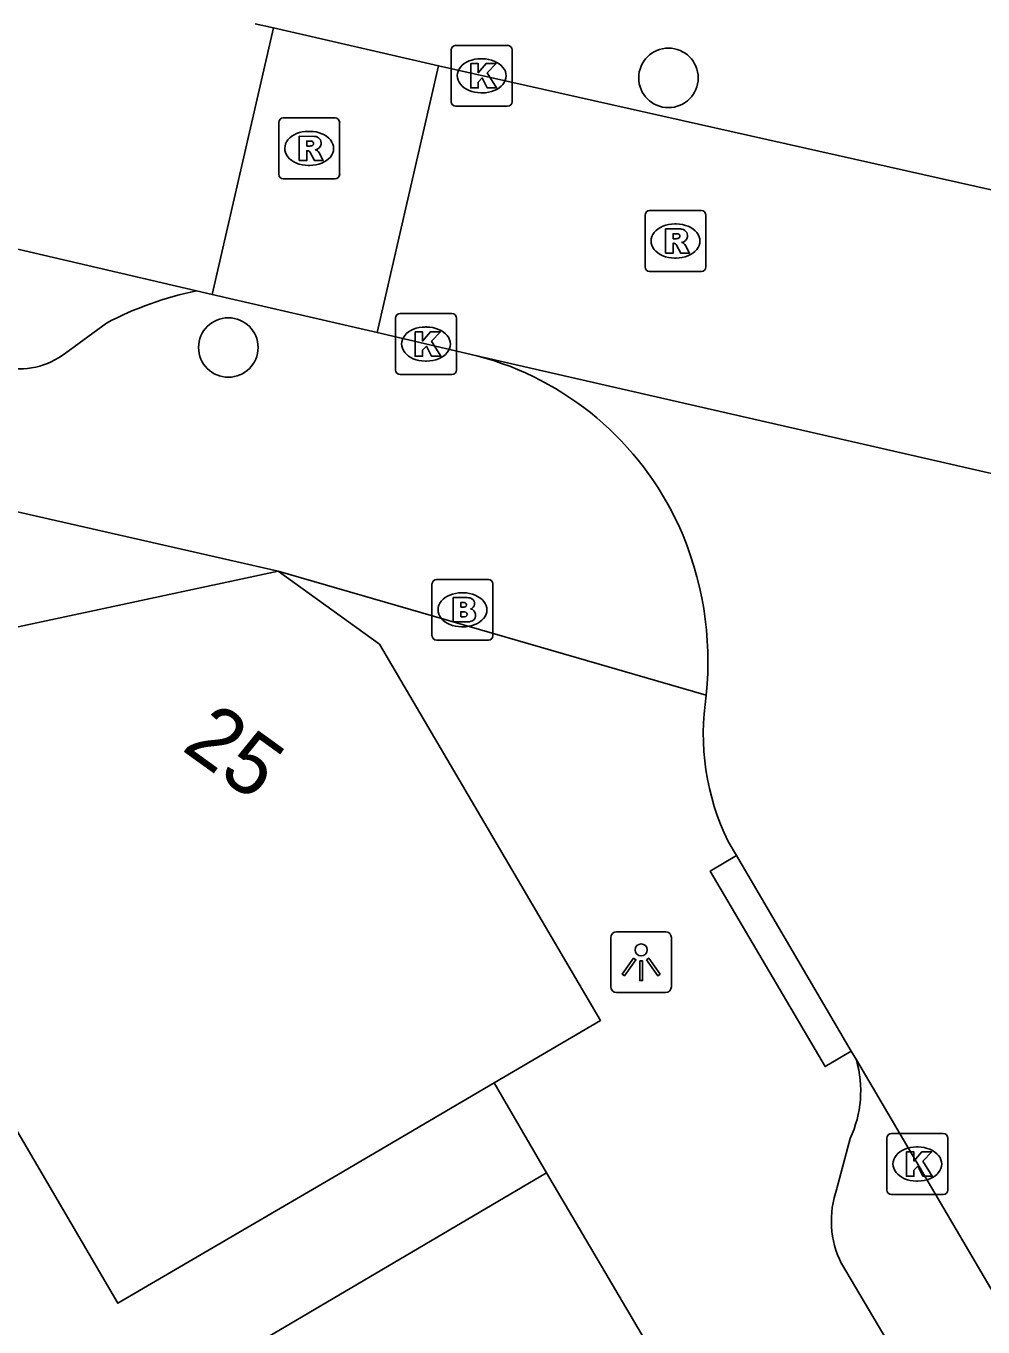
# Model space of a CAD drawing. Extents: x 159718 to 160783, y 383290 to 384030.
# Drawn here: x 160111.85 to 160127.57, y 383460.37 to 383481.74 of the extents above; entities that cross this region are included whole.
import ezdxf

# ---------------------------------------------------------------- set-up
doc = ezdxf.new("R2010")
doc.units = 0
for name, color, linetype in [('IMGEO_Boom', 7, 'Continuous'), ('IMGEO_Brandkraan', 7, 'Continuous'), ('IMGEO_Kolk', 7, 'Continuous'), ('IMGEO_Lichtpunt', 7, 'Continuous'), ('IMGEO_Pand', 7, 'Continuous'), ('IMGEO_Pand_nummerreeks', 7, 'Continuous'), ('IMGEO_Rijbaan_lokaal_open', 7, 'Continuous'), ('IMGEO_Rioolput', 7, 'Continuous'), ('IMGEO_Voetpad_open', 7, 'Continuous')]:
    doc.layers.add(name, color=color, linetype=linetype)

msp = doc.modelspace()

# ---------------------------------------------------------------- linework, layer by layer
at = {"layer": 'IMGEO_Boom'}
for centre in [(160122.406, 383480.893), (160115.175, 383476.462)]:
    msp.add_circle(centre, 0.489, dxfattribs=at)
at = {"layer": 'IMGEO_Brandkraan'}
for p, q in [((160118.521, 383471.726), (160118.521, 383472.578)), ((160118.596, 383472.652), (160119.448, 383472.652)), ((160119.522, 383472.578), (160119.522, 383471.726)), ((160119.009, 383472.432), (160119.034, 383472.432)), ((160119.032, 383471.872), (160119.007, 383471.872)), ((160119.448, 383471.652), (160118.596, 383471.652))]:
    msp.add_line(p, q, dxfattribs=at)
for points in [[(160118.521, 383471.726), (160118.521, 383472.578)], [(160118.596, 383472.652), (160119.448, 383472.652)], [(160119.522, 383472.578), (160119.522, 383471.726)], [(160118.869, 383472.352), (160118.869, 383471.952), (160119.082, 383471.952)], [(160119.1, 383472.352), (160118.869, 383472.352)], [(160119.048, 383472.271), (160118.994, 383472.271), (160118.994, 383472.195)], [(160118.994, 383472.195), (160119.047, 383472.195)], [(160119.056, 383472.119), (160118.994, 383472.119), (160118.994, 383472.038)], [(160118.994, 383472.038), (160119.056, 383472.038)], [(160119.448, 383471.652), (160118.596, 383471.652)]]:
    msp.add_lwpolyline(points, dxfattribs=at)
for centre, radius, start, end in [((160118.598, 383472.576), 0.0765, 91.552, 178.448), ((160118.598, 383472.576), 0.0765, 91.552, 178.448), ((160119.446, 383472.576), 0.0765, 1.552, 88.448), ((160119.446, 383472.576), 0.0765, 1.552, 88.448), ((160119.049, 383472.233), 0.0379, 267.8285, 90.9355), ((160119.104, 383472.207), 0.145, 59.4692, 91.5367), ((160119.129, 383472.254), 0.0922, 285.5137, 58.1501), ((160119.134, 383472.062), 0.105, 301.3115, 78.989), ((160119.057, 383472.078), 0.0404, 269.8759, 90.5077), ((160119.088, 383472.203), 0.251, 268.6676, 293.5347), ((160118.598, 383471.728), 0.0765, 181.552, 268.448), ((160118.598, 383471.728), 0.0765, 181.552, 268.448), ((160119.446, 383471.728), 0.0765, 271.552, 358.448), ((160119.446, 383471.728), 0.0765, 271.552, 358.448)]:
    msp.add_arc(centre, radius, start, end, dxfattribs=at)
for centre, major_axis, ratio, start_param, end_param in [((160119.008, 383472.152), (-0.387, 0.002), 0.722429, 4.712389, 7.853982), ((160119.033, 383472.152), (-0.39, 0.002), 0.717154, 1.570796, 4.712389)]:
    msp.add_ellipse(centre, major_axis=major_axis, ratio=ratio, start_param=start_param, end_param=end_param, dxfattribs=at)
at = {"layer": 'IMGEO_Kolk'}
for p, q in [((160118.837, 383480.501), (160118.837, 383481.353)), ((160118.912, 383481.427), (160119.764, 383481.427)), ((160119.838, 383481.353), (160119.838, 383480.501)), ((160119.325, 383481.207), (160119.35, 383481.207)), ((160119.348, 383480.647), (160119.323, 383480.647)), ((160119.764, 383480.427), (160118.912, 383480.427)), ((160117.922, 383476.093), (160117.922, 383476.945)), ((160117.997, 383477.019), (160118.849, 383477.019)), ((160118.923, 383476.945), (160118.923, 383476.093)), ((160118.41, 383476.799), (160118.435, 383476.799)), ((160118.433, 383476.239), (160118.408, 383476.239)), ((160118.849, 383476.019), (160117.997, 383476.019)), ((160125.994, 383462.619), (160125.994, 383463.471)), ((160126.069, 383463.545), (160126.921, 383463.545)), ((160126.995, 383463.471), (160126.995, 383462.619)), ((160126.482, 383463.325), (160126.507, 383463.325)), ((160126.505, 383462.765), (160126.48, 383462.765)), ((160126.921, 383462.545), (160126.069, 383462.545))]:
    msp.add_line(p, q, dxfattribs=at)
for points in [[(160118.837, 383480.501), (160118.837, 383481.353)], [(160118.912, 383481.427), (160119.764, 383481.427)], [(160119.838, 383481.353), (160119.838, 383480.501)], [(160119.158, 383481.127), (160119.281, 383481.127), (160119.281, 383480.976), (160119.411, 383481.127), (160119.575, 383481.127), (160119.429, 383480.976), (160119.582, 383480.727), (160119.43, 383480.727), (160119.345, 383480.891), (160119.281, 383480.824), (160119.281, 383480.727), (160119.158, 383480.727), (160119.158, 383481.127)], [(160119.764, 383480.427), (160118.912, 383480.427)], [(160117.922, 383476.093), (160117.922, 383476.945)], [(160117.997, 383477.019), (160118.849, 383477.019)], [(160118.923, 383476.945), (160118.923, 383476.093)], [(160118.243, 383476.719), (160118.366, 383476.719), (160118.366, 383476.568), (160118.496, 383476.719), (160118.66, 383476.719), (160118.514, 383476.568), (160118.667, 383476.319), (160118.515, 383476.319), (160118.43, 383476.483), (160118.366, 383476.416), (160118.366, 383476.319), (160118.243, 383476.319), (160118.243, 383476.719)], [(160118.849, 383476.019), (160117.997, 383476.019)], [(160125.994, 383462.619), (160125.994, 383463.471)], [(160126.069, 383463.545), (160126.921, 383463.545)], [(160126.995, 383463.471), (160126.995, 383462.619)], [(160126.315, 383463.245), (160126.438, 383463.245), (160126.438, 383463.094), (160126.568, 383463.245), (160126.732, 383463.245), (160126.586, 383463.094), (160126.739, 383462.845), (160126.587, 383462.845), (160126.502, 383463.009), (160126.438, 383462.942), (160126.438, 383462.845), (160126.315, 383462.845), (160126.315, 383463.245)], [(160126.921, 383462.545), (160126.069, 383462.545)]]:
    msp.add_lwpolyline(points, dxfattribs=at)
for centre, start, end in [((160118.914, 383481.351), 91.552, 178.448), ((160118.914, 383481.351), 91.552, 178.448), ((160119.762, 383481.351), 1.552, 88.448), ((160119.762, 383481.351), 1.552, 88.448), ((160118.914, 383480.503), 181.552, 268.448), ((160118.914, 383480.503), 181.552, 268.448), ((160119.762, 383480.503), 271.552, 358.448), ((160119.762, 383480.503), 271.552, 358.448), ((160117.999, 383476.943), 91.552, 178.448), ((160117.999, 383476.943), 91.552, 178.448), ((160118.847, 383476.943), 1.552, 88.448), ((160118.847, 383476.943), 1.552, 88.448), ((160117.999, 383476.095), 181.552, 268.448), ((160117.999, 383476.095), 181.552, 268.448), ((160118.847, 383476.095), 271.552, 358.448), ((160118.847, 383476.095), 271.552, 358.448), ((160126.071, 383463.469), 91.552, 178.448), ((160126.071, 383463.469), 91.552, 178.448), ((160126.919, 383463.469), 1.552, 88.448), ((160126.919, 383463.469), 1.552, 88.448), ((160126.071, 383462.621), 181.552, 268.448), ((160126.071, 383462.621), 181.552, 268.448), ((160126.919, 383462.621), 271.552, 358.448), ((160126.919, 383462.621), 271.552, 358.448)]:
    msp.add_arc(centre, 0.0765, start, end, dxfattribs=at)
for centre, major_axis, ratio, start_param, end_param in [((160119.324, 383480.927), (-0.387, 0.002), 0.722429, 4.712389, 7.853982), ((160119.349, 383480.927), (-0.39, 0.002), 0.717154, 1.570796, 4.712389), ((160118.409, 383476.519), (-0.387, 0.002), 0.722429, 4.712389, 7.853982), ((160118.434, 383476.519), (-0.39, 0.002), 0.717154, 1.570796, 4.712389), ((160126.481, 383463.045), (-0.387, 0.002), 0.722429, 4.712389, 7.853982), ((160126.506, 383463.045), (-0.39, 0.002), 0.717154, 1.570796, 4.712389)]:
    msp.add_ellipse(centre, major_axis=major_axis, ratio=ratio, start_param=start_param, end_param=end_param, dxfattribs=at)
at = {"layer": 'IMGEO_Lichtpunt'}
for p, q in [((160122.36, 383466.86), (160121.552, 383466.86)), ((160122.36, 383466.86), (160121.552, 383466.86)), ((160121.458, 383466.765), (160121.458, 383465.958)), ((160121.458, 383466.765), (160121.458, 383465.958)), ((160122.454, 383465.958), (160122.454, 383466.765)), ((160122.454, 383465.958), (160122.454, 383466.765)), ((160121.552, 383465.864), (160122.36, 383465.864)), ((160121.552, 383465.864), (160122.36, 383465.864))]:
    msp.add_line(p, q, dxfattribs=at)
for points in [[(160121.832, 383466.429), (160121.871, 383466.401), (160121.683, 383466.139), (160121.645, 383466.166), (160121.832, 383466.429)], [(160121.934, 383466.381), (160121.981, 383466.381), (160121.981, 383466.059), (160121.934, 383466.059), (160121.934, 383466.381)], [(160122.044, 383466.401), (160122.082, 383466.428), (160122.269, 383466.166), (160122.23, 383466.138), (160122.044, 383466.401)]]:
    msp.add_lwpolyline(points, dxfattribs=at)
msp.add_circle((160121.957, 383466.563), 0.0994, dxfattribs=at)
for centre, start, end in [((160121.552, 383466.765), 90, 180), ((160121.552, 383466.765), 90, 180), ((160122.36, 383466.765), 0, 90), ((160122.36, 383466.765), 0, 90), ((160121.552, 383465.958), 180, 270), ((160121.552, 383465.958), 180, 270), ((160122.36, 383465.958), 270, 0), ((160122.36, 383465.958), 270, 360)]:
    msp.add_arc(centre, 0.0946, start, end, dxfattribs=at)
at = {"layer": 'IMGEO_Pand'}
for points in [[(160115.993, 383472.788), (160107.52, 383470.974), (160108.363, 383474.524)], [(160115.993, 383472.788), (160117.657, 383471.587), (160121.29, 383465.405), (160119.544, 383464.378)], [(160119.544, 383464.378), (160116.981, 383462.87), (160113.362, 383460.758), (160111.515, 383463.912), (160107.52, 383461.562), (160106.899, 383462.618), (160104.842, 383466.115), (160102.458, 383466.683), (160102.051, 383466.78)], [(160123.801, 383457.127), (160119.492, 383454.592), (160116.953, 383453.098), (160115.556, 383455.612), (160113.326, 383454.3), (160110.771, 383452.796), (160109.958, 383454.177), (160108.721, 383456.279), (160113.525, 383459.105), (160113.635, 383458.918), (160116.096, 383460.366), (160120.405, 383462.901)], [(160123.801, 383457.127), (160120.405, 383462.901)]]:
    msp.add_lwpolyline(points, dxfattribs=at)
at = {"layer": 'IMGEO_Rijbaan_lokaal_open'}
for points in [[(160076.614, 383486.267), (160114.655, 383477.395)], [(160115.615, 383481.783), (160115.92, 383481.713)], [(160114.912, 383477.335), (160115.92, 383481.713)], [(160115.92, 383481.713), (160118.629, 383481.089)], [(160118.629, 383481.089), (160117.62, 383476.707)], [(160118.629, 383481.089), (160134.274, 383477.578)], [(160114.912, 383477.335), (160114.655, 383477.395)], [(160117.62, 383476.707), (160114.912, 383477.335)], [(160119.26, 383476.327), (160117.62, 383476.707)], [(160132.838, 383473.219), (160119.26, 383476.327)], [(160123.386, 383468.345), (160123.523, 383468.112)], [(160123.523, 383468.112), (160125.409, 383464.899)], [(160125.409, 383464.899), (160125.493, 383464.755)], [(160125.493, 383464.755), (160139.179, 383441.454)]]:
    msp.add_lwpolyline(points, dxfattribs=at)
for centre, radius, start, end in [((160117.967, 383471.429), 5.066, 24.5802, 75.2127), ((160117.607, 383471.299), 5.448, 354.229, 24.2483), ((160127.035, 383470.119), 4.057, 171.0415, 205.9315)]:
    msp.add_arc(centre, radius, start, end, dxfattribs=at)
at = {"layer": 'IMGEO_Rioolput'}
for p, q in [((160116.003, 383479.308), (160116.003, 383480.16)), ((160116.078, 383480.234), (160116.93, 383480.234)), ((160117.004, 383480.16), (160117.004, 383479.308)), ((160116.491, 383480.014), (160116.516, 383480.014)), ((160116.514, 383479.454), (160116.489, 383479.454)), ((160116.93, 383479.234), (160116.078, 383479.234)), ((160122.021, 383477.786), (160122.021, 383478.638)), ((160122.096, 383478.712), (160122.948, 383478.712)), ((160123.022, 383478.638), (160123.022, 383477.786)), ((160122.509, 383478.492), (160122.534, 383478.492)), ((160122.532, 383477.932), (160122.507, 383477.932)), ((160122.948, 383477.712), (160122.096, 383477.712))]:
    msp.add_line(p, q, dxfattribs=at)
for points in [[(160116.003, 383479.308), (160116.003, 383480.16)], [(160116.078, 383480.234), (160116.93, 383480.234)], [(160117.004, 383480.16), (160117.004, 383479.308)], [(160116.592, 383479.932), (160116.34, 383479.934), (160116.34, 383479.534)], [(160116.518, 383479.853), (160116.464, 383479.853), (160116.464, 383479.772)], [(160116.34, 383479.534), (160116.464, 383479.534), (160116.464, 383479.696), (160116.475, 383479.696)], [(160116.464, 383479.772), (160116.516, 383479.772)], [(160116.522, 383479.667), (160116.593, 383479.534), (160116.733, 383479.534), (160116.668, 383479.66)], [(160116.93, 383479.234), (160116.078, 383479.234)], [(160122.021, 383477.786), (160122.021, 383478.638)], [(160122.096, 383478.712), (160122.948, 383478.712)], [(160123.022, 383478.638), (160123.022, 383477.786)], [(160122.61, 383478.41), (160122.358, 383478.412), (160122.358, 383478.012)], [(160122.358, 383478.012), (160122.482, 383478.012), (160122.482, 383478.174), (160122.493, 383478.174)], [(160122.536, 383478.331), (160122.482, 383478.331), (160122.482, 383478.25)], [(160122.482, 383478.25), (160122.534, 383478.25)], [(160122.54, 383478.145), (160122.611, 383478.012), (160122.751, 383478.012), (160122.686, 383478.138)], [(160122.948, 383477.712), (160122.096, 383477.712)]]:
    msp.add_lwpolyline(points, dxfattribs=at)
for centre, radius, start, end in [((160116.08, 383480.158), 0.0765, 91.552, 178.448), ((160116.08, 383480.158), 0.0765, 91.552, 178.448), ((160116.928, 383480.158), 0.0765, 1.552, 88.448), ((160116.928, 383480.158), 0.0765, 1.552, 88.448), ((160116.524, 383479.757), 0.0964, 77.0061, 93.1865), ((160116.538, 383479.814), 0.0378, 276.6634, 79.6772), ((160116.591, 383479.822), 0.109, 350.3612, 89.416), ((160116.474, 383479.643), 0.0533, 26.0293, 88.6989), ((160116.5, 383479.961), 0.19, 274.7715, 282.9687), ((160116.589, 383479.822), 0.112, 277.5842, 350.9817), ((160116.573, 383479.607), 0.108, 29.5134, 73.7905), ((160116.08, 383479.31), 0.0765, 181.552, 268.448), ((160116.08, 383479.31), 0.0765, 181.552, 268.448), ((160116.928, 383479.31), 0.0765, 271.552, 358.448), ((160116.928, 383479.31), 0.0765, 271.552, 358.448), ((160122.098, 383478.636), 0.0765, 91.552, 178.448), ((160122.098, 383478.636), 0.0765, 91.552, 178.448), ((160122.946, 383478.636), 0.0765, 1.552, 88.448), ((160122.946, 383478.636), 0.0765, 1.552, 88.448), ((160122.609, 383478.3), 0.109, 350.3612, 89.416), ((160122.492, 383478.121), 0.0533, 26.0293, 88.6989), ((160122.518, 383478.439), 0.19, 274.7715, 282.9687), ((160122.542, 383478.235), 0.0964, 77.0061, 93.1865), ((160122.556, 383478.292), 0.0378, 276.6634, 79.6772), ((160122.607, 383478.3), 0.112, 277.5842, 350.9817), ((160122.591, 383478.085), 0.108, 29.5134, 73.7905), ((160122.098, 383477.788), 0.0765, 181.552, 268.448), ((160122.098, 383477.788), 0.0765, 181.552, 268.448), ((160122.946, 383477.788), 0.0765, 271.552, 358.448), ((160122.946, 383477.788), 0.0765, 271.552, 358.448)]:
    msp.add_arc(centre, radius, start, end, dxfattribs=at)
for centre, major_axis, ratio, start_param, end_param in [((160116.49, 383479.734), (-0.387, 0.002), 0.722429, 4.712389, 7.853982), ((160116.515, 383479.734), (-0.39, 0.002), 0.717154, 1.570796, 4.712389), ((160122.508, 383478.212), (-0.387, 0.002), 0.722429, 4.712389, 7.853982), ((160122.533, 383478.212), (-0.39, 0.002), 0.717154, 1.570796, 4.712389)]:
    msp.add_ellipse(centre, major_axis=major_axis, ratio=ratio, start_param=start_param, end_param=end_param, dxfattribs=at)
at = {"layer": 'IMGEO_Voetpad_open'}
for points in [[(160113.173, 383476.864), (160112.5, 383476.369)], [(160108.363, 383474.524), (160115.993, 383472.788)], [(160115.993, 383472.788), (160123.027, 383470.751)], [(160125.409, 383464.899), (160124.979, 383464.645), (160123.093, 383467.858), (160123.523, 383468.112)], [(160120.405, 383462.901), (160119.544, 383464.378)], [(160125.174, 383462.64), (160125.391, 383463.465)], [(160136.342, 383442.643), (160125.249, 383461.408)]]:
    msp.add_lwpolyline(points, dxfattribs=at)
for centre, radius, start, end in [((160115.808, 383471.842), 5.671, 101.7344, 117.6907), ((160111.743, 383477.354), 1.242, 257.3366, 307.5441), ((160123.707, 383464.247), 1.857, 335.0906, 15.8675), ((160126.648, 383462.111), 1.566, 160.2709, 206.6964)]:
    msp.add_arc(centre, radius, start, end, dxfattribs=at)

# ---------------------------------------------------------------- texts
at = {"layer": 'IMGEO_Pand_nummerreeks'}
msp.add_text('25', height=1, rotation=324.1799, dxfattribs=at).set_placement((160114.389, 383469.859))

doc.saveas('drawing.dxf')
